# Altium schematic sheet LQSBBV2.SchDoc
size A3; SheetNumber: 0; SheetTotal: 0
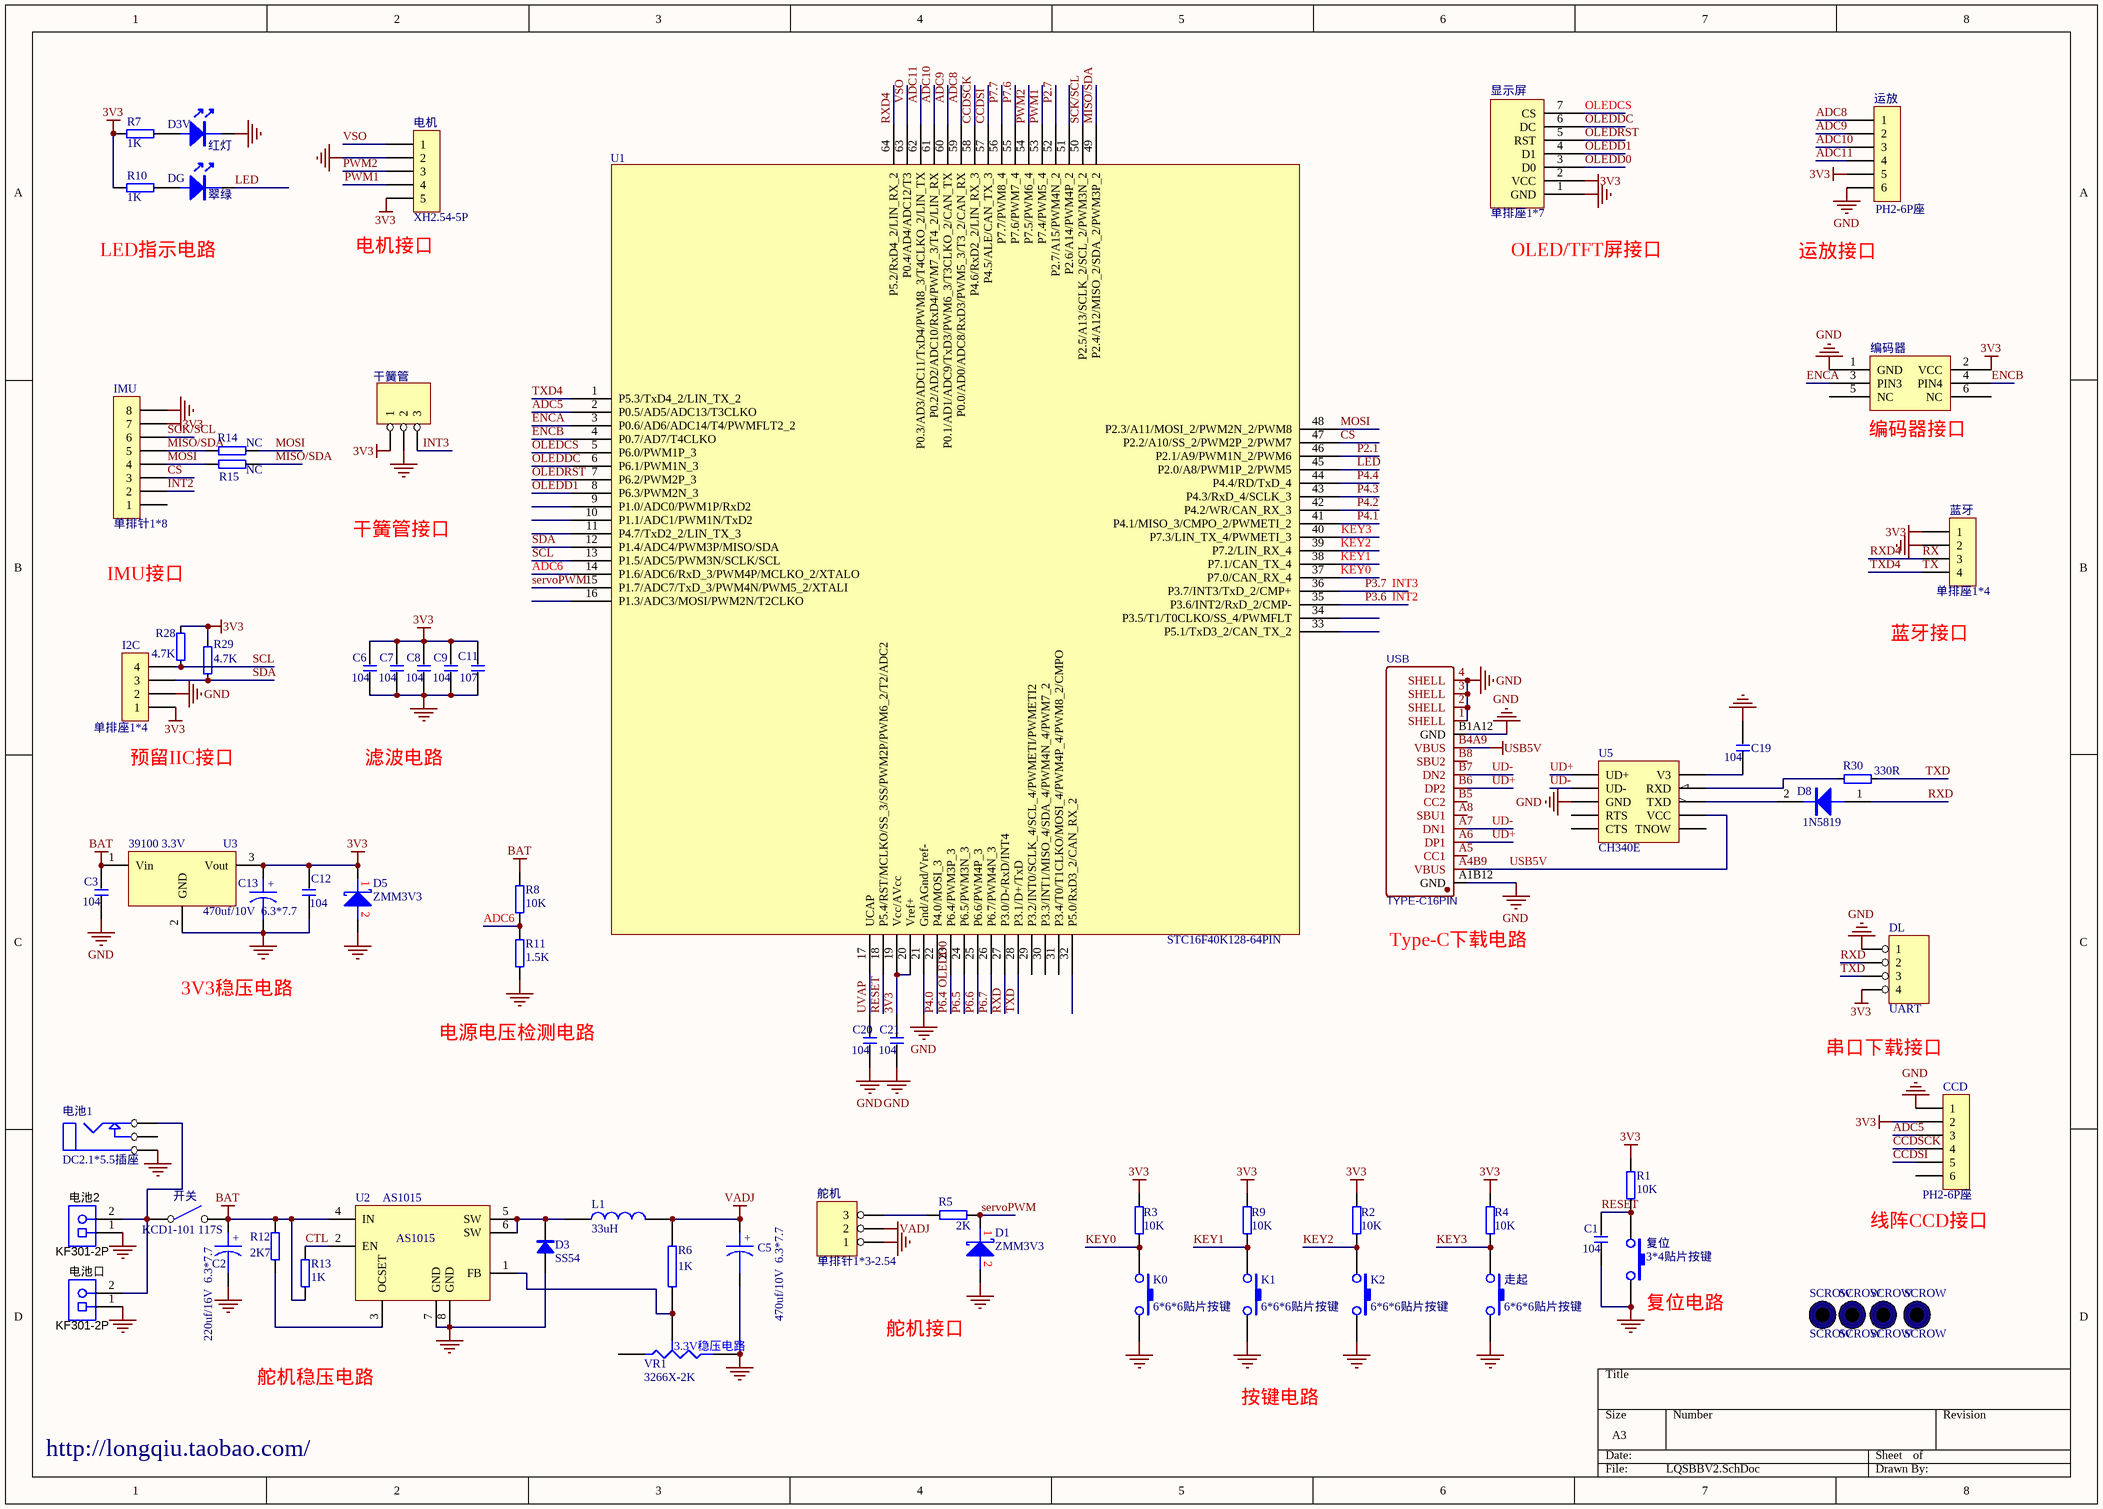
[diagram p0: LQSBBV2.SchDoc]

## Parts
(Parts that share a designator on the sheet are numbered #1, #2 ... from top to bottom, then left to right.)
C1  104  [0805]
C2  220uf/16V  6.3*7.7  [LQ_C6d3X7d7]
C3  104  [0805]
C5  470uf/10V  6.3*7.7  [LQ_C6d3X7d7]
C6  104  [0805]
C7  104  [0805]
C8  104  [0805]
C9  104  [0805]
C11  107  [LQ_C1210T]
C12  104  [0805]
C13  470uf/10V  6.3*7.7  [LQ_C6d3X7d7]
C19  104  [0805]
C20  104  [0805]
C21  104  [0805]
CCD  PH2-6P座  [LQ_PH2-6P]
D1  ZMM3V3  [LQ_D1206Z]
D3  SS54  [SMB]
D3V  红灯  [LQ_0603D]
D5  ZMM3V3  [LQ_D1206Z]
D8  1N5819  [LQ_D1206]
DG  翠绿  [LQ_0603D]
DL  UART  [SIP4]
I2C  单排座1*4  [LQ_SIP4]
IMU  单排针1*8  [LQ_SIP8n]
K0  6*6*6贴片按键  [LQ_BT4SMT]
K1  6*6*6贴片按键  [LQ_BT4SMT]
K2  6*6*6贴片按键  [LQ_BT4SMT]
L1  33uH  [LQ_L7X7]
R1  10K  [0805]
R2  10K  [0805]
R3  10K  [0805]
R4  10K  [0805]
R5  2K  [0805]
R6  1K  [LQ_R0603]
R7  1K  [0805]
R8  10K  [0805]
R9  10K  [0805]
R10  1K  [0805]
R11  1.5K  [0805]
R12  2K7  [0805]
R13  1K  [0805]
R14  NC  [0805]
R15  NC  [0805]
R28  4.7K  [0805]
R29  4.7K  [0805]
R30  330R  [0805]
SCROW#1  SCROW  [LQ_SCROW3&5mm]
SCROW#2  SCROW  [LQ_SCROW3&5mm]
SCROW#3  SCROW  [LQ_SCROW3&5mm]
SCROW#4  SCROW  [LQ_SCROW3&5mm]
U1  STC16F40K128-64PIN  [LQ_LQFP64S]
U2  AS1015  [SO-8]
U3  39100 3.3V  [SOT223_M]
U5  CH340E  [LQ_MSOP10]
USB  TYPE-C16PIN  [USB-C-SMD_TYPE-C16PIN]
VR1  3266X-2K  [lq_3266]
复位  3*4贴片按键  [LQ_BT2SMT3X4]
干簧管  单排针1*3-2.54  [LQ_SIP3]  (value not drawn)
开关  KCD1-101 117S  [LQ_KCD1-101 117S]
显示屏  单排座1*7-2.54  [LQ_OLED&TFTSPI]  (value not drawn)
电机  XH2.54-5P  [LQ_XH254-5P]
电池1  DC2.1*5.5插座  [LQ_DC5.5x2.1]
电池2  KF301-2P  [LQ_PIN2]
电池口  KF301-2P  [LQ_PIN2]
编码器  双排针3X2  [LQ_ENCODER]  (value not drawn)
舵机  单排针1*3-2.54  [LQ_SIP3]
蓝牙  单排座1*4  [LQ_SIP4]
走起  6*6*6贴片按键  [LQ_BT4SMT]
运放  PH2-6P座  [LQ_PH2-6P]

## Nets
3V3: C6.1 C7.1 C8.1 C9.1 C11.1 C12.1 C13.1 C21.1 CCD.2 D5.1 DL.4 I2C.1 IMU.7 R1.1 R2.2 R3.2 R4.2 R7.1 R9.2 R10.1 R28.2 R29.2 U1.19(Vcc/AVcc) U1.20(Vref+) U3.3(Vout) 干簧管.1 显示屏.2(VCC) 电机.5 编码器.2(VCC) 蓝牙.1 运放.5
BAT: C2.1 C3.1 R8.1 R12.1 R13.2 U2.4(IN) U3.1(Vin) 开关.2(NO)
GND: C1.2 C2.2 C3.2 C5.2 C6.2 C7.2 C8.2 C9.2 C11.2 C12.2 C13.2 C19.1 C20.2 C21.2 CCD.1 D1.2 D3.1(A) D3V.2 D5.2 DL.1 I2C.2 IMU.8 K0.2 K1.2 K2.2 R11.2 U1.21(Gnd/AGnd/Vref-) U2.7(GND) U2.8(GND) U3.2(GND) U5.3(GND) USB.1(SHELL) USB.2(SHELL) USB.3(SHELL) USB.4(SHELL) USB.A1B12(GND) USB.B1A12(GND) VR1.2(B) 复位.2 干簧管.2 显示屏.1(GND) 电机.2 电池1.3(C) 电池2.1 电池口.1 编码器.1(GND) 舵机.1 蓝牙.2 走起.2 运放.6
USB5V: U5.7(VCC) USB.A4B9(VBUS) USB.B4A9(VBUS)
VADJ: C5.1 L1.2 R6.2 舵机.2
ADC5: CCD.3 U1.2(P0.5/AD5/ADC13/T3CLKO)
ADC6: R8.2 R11.1 U1.14(P1.6/ADC6/RxD_3/PWM4P/MCLKO_2/XTALO)
ADC8: U1.59(P0.0/AD0/ADC8/RxD3/PWM5_3/T3_2/CAN_RX) 运放.1
ADC9: U1.60(P0.1/AD1/ADC9/TxD3/PWM6_3/T3CLKO_2/CAN_TX) 运放.2
ADC10: U1.61(P0.2/AD2/ADC10/RxD4/PWM7_3/T4_2/LIN_RX) 运放.3
ADC11: U1.62(P0.3/AD3/ADC11/TxD4/PWM8_3/T4CLKO_2/LIN_TX) 运放.4
CCDSCK: CCD.4 U1.58(P4.6/RxD2_2/LIN_RX_3)
CCDSI: CCD.5 U1.57(P4.5/ALE/CAN_TX_3)
CS: IMU.3 U1.47(P2.2/A10/SS_2/PWM2P_2/PWM7)
CTL: R13.1 U2.2(EN)
ENCA: U1.3(P0.6/AD6/ADC14/T4/PWMFLT2_2) 编码器.3(PIN3)
ENCB: U1.4(P0.7/AD7/T4CLKO) 编码器.4(PIN4)
INT2: IMU.2 U1.35(P3.6/INT2/RxD_2/CMP-)  [also labelled P3.6]
INT3: U1.36(P3.7/INT3/TxD_2/CMP+) 干簧管.3  [also labelled P3.7]
KEY0: K0.1 R3.1 U1.37(P7.0/CAN_RX_4)
KEY1: K1.1 R9.1 U1.38(P7.1/CAN_TX_4)
KEY2: K2.1 R2.1 U1.39(P7.2/LIN_RX_4)
KEY3: R4.1 U1.40(P7.3/LIN_TX_4/PWMETI_3) 走起.1
LED: DG.2 U1.45(P2.0/A8/PWM1P_2/PWM5)
MISO/SDA: IMU.5 R14.2 R15.1 U1.49(P2.4/A12/MISO_2/SDA_2/PWM3P_2)
MOSI: IMU.4 R14.1 R15.2 U1.48(P2.3/A11/MOSI_2/PWM2N_2/PWM8)
OLEDCS: U1.5(P6.0/PWM1P_3) 显示屏.7(CS)
OLEDD0: U1.23(P6.4/PWM3P_3) 显示屏.3(D0)  [also labelled P6.4]
OLEDD1: U1.8(P6.3/PWM2N_3) 显示屏.4(D1)
OLEDDC: U1.6(P6.1/PWM1N_3) 显示屏.6(DC)
OLEDRST: U1.7(P6.2/PWM2P_3) 显示屏.5(RST)
P2.1: U1.46(P2.1/A9/PWM1N_2/PWM6)
P2.7: U1.52(P2.7/A15/PWM4N_2)
P4.0: U1.22(P4.0/MOSI_3)
P4.1: U1.41(P4.1/MISO_3/CMPO_2/PWMETI_2)
P4.2: U1.42(P4.2/WR/CAN_RX_3)
P4.3: U1.43(P4.3/RxD_4/SCLK_3)
P4.4: U1.44(P4.4/RD/TxD_4)
P6.5: U1.24(P6.5/PWM3N_3)
P6.6: U1.25(P6.6/PWM4P_3)
P6.7: U1.26(P6.7/PWM4N_3)
P7.6: U1.55(P7.6/PWM7_4)
P7.7: U1.56(P7.7/PWM8_4)
PWM1: U1.53(P7.4/PWM5_4) 电机.4
PWM2: U1.54(P7.5/PWM6_4) 电机.3
RESET: C1.1 R1.2 U1.18(P5.4/RST/MCLKO/SS_3/SS/PWM2P/PWM6_2/T2/ADC2) 复位.1
RX: U1.64(P5.2/RxD4_2/LIN_RX_2) 蓝牙.3  [also labelled RXD4]
RXD: D8.1(A) DL.2 U1.27(P3.0/D-/RxD/INT4)
SCK/SCL: IMU.6 U1.50(P2.5/A13/SCLK_2/SCL_2/PWM3N_2)
SCL: I2C.4 R28.1 U1.13(P1.5/ADC5/PWM3N/SCLK/SCL)
SDA: I2C.3 R29.1 U1.12(P1.4/ADC4/PWM3P/MISO/SDA)
servoPWM: D1.1 R5.2 U1.15(P1.7/ADC7/TxD_3/PWM4N/PWM5_2/XTALI)
TX: U1.1(P5.3/TxD4_2/LIN_TX_2) 蓝牙.4  [also labelled TXD4]
TXD: DL.3 R30.2 U1.28(P3.1/D+/TxD)
UD+: U5.1(UD+) USB.A6(DP1) USB.B6(DP2)
UD-: U5.2(UD-) USB.A7(DN1) USB.B7(DN2)
UVAP: C20.1 U1.17(UCAP)
VSO: U1.63(P0.4/AD4/ADC12/T3) 电机.1
NetC19_2: C19.2 U5.10(V3)
NetD3_2: D3.2(K) L1.1 U2.5(SW) U2.6(SW)
NetD3V_1: D3V.1 R7.2
NetD8_2: D8.2(K) U5.8(TXD)
NetDG_1: DG.1 R10.2
NetR5_1: R5.1 舵机.3
NetR6_1: R6.1 U2.1(FB) VR1.3(TAP)
NetR12_2: R12.2 U2.3(OCSET)
NetR30_1: R30.1 U5.9(RXD)
Net开关_1: 开关.1(COMMON) 电池1.1(A) 电池2.2 电池口.2

Not connected (* = marked no-connect by the designer): CCD 6; IMU 1; SCROW#1 1; SCROW#2 1; SCROW#3 1; SCROW#4 1; U1 9(P1.0/ADC0/PWM1P/RxD2) 10(P1.1/ADC1/PWM1N/TxD2) 11(P4.7/TxD2_2/LIN_TX_3) 16(P1.3/ADC3/MOSI/PWM2N/T2CLKO) 29(P3.2/INT0/SCLK_4/SCL_4/PWMETI/PWMETI2) 30(P3.3/INT1/MISO_4/SDA_4/PWM4N_4/PWM7_2) 31(P3.4/T0/T1CLKO/MOSI_4/PWM4P_4/PWM8_2/CMPO) 32(P5.0/RxD3_2/CAN_RX_2) 33(P5.1/TxD3_2/CAN_TX_2) 34(P3.5/T1/T0CLKO/SS_4/PWMFLT) 51(P2.6/A14/PWM4P_2); U5 4(RTS) 5(CTS) 6(TNOW); USB A5(CC1) A8(SBU1) B5(CC2) B8(SBU2); VR1 1(A); 电池1 2(B); 编码器 5(NC) 6(NC)

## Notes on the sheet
- (near 显示屏) 单排座1*7
- LED指示电路
- (near 电机) 电机接口
- (near 显示屏) OLED/TFT屏接口
- 运放接口
- (near 编码器) 编码器接口
- IMU接口
- 干簧管接口
- 蓝牙接口
- (near I2C) 预留IIC接口
- 滤波电路
- (near USB) Type-C下载电路
- 3V3稳压电路
- 电源电压检测电路
- 串口下载接口
- (near CCD) 线阵CCD接口
- (near 复位) 复位电路
- 舵机稳压电路
- (near VR1) 3.3V稳压电路
- 舵机接口
- http://longqiu.taobao.com/
- 按键电路

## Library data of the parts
C1 C3 C6-C9 C11 C12 C19-C21 = LQ_CAP: CAP
C2 C5 C13 = CAPACITOR POL: Capacitor
CCD 运放 = CON6: Connector
D1 D5 = LQ_Z: Schottky Diode
D3 = SS54: 肖特基二极管; 版权归属: 源创客; 属性: 40V/3A
D3V DG = LQ_LED
D8 = DIODE
DL = 4 HEADER
I2C 蓝牙 = CON4: Connector
IMU = CON8: Connector
K0-K2 复位 走起 = SW-PB
L1 = INDUCTOR
R1-R5 R8 R9 R11 R12 R14 R15 = LQ_RES: 1K
R6 = RES2
R7 R10 R13 = LQ_RES
R28-R30 = RES
SCROW#1-SCROW#4 = SCROW: Connector
U3 = VOLTREG
USB = TYPE-C16PIN: BOM_Manufacturer: SHOU HAN; Contributor: LCSC
VR1 = RESISTOR TAPPED
干簧管 舵机 = HEADER 3
开关 = SW SPST
显示屏 = LQ_OLED128X64
电机 = CON5: Connector
电池1 = PHONEJACK
电池2 电池口 = 691 101 710 002: Manufacturer: Wurth Elektronik eiSos; SymbolCreator: a0412235; CompType: Terminal Block; U/M: EA
编码器 = Component_1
